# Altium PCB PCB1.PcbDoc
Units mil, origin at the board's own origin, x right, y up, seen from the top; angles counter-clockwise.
Board outline 2495 x 1003.43 mil, 4 copper layers (Top Layer, GND, 3.3V, Bottom Layer), stack 61.581 mil thick; 63 components, 70 nets, 242 pads, 36 vias.
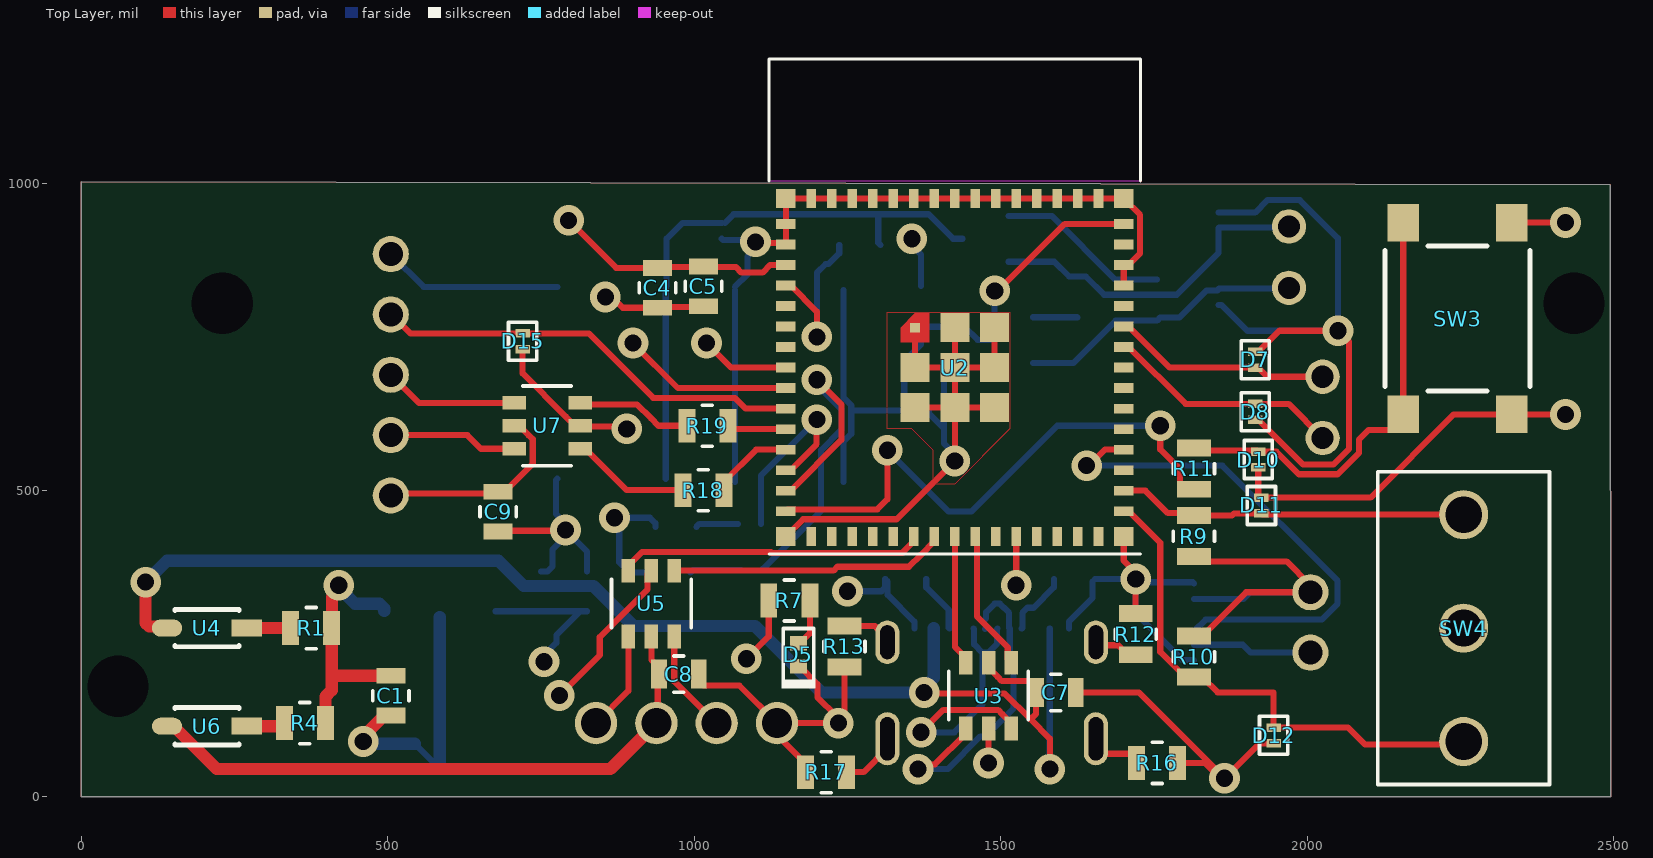
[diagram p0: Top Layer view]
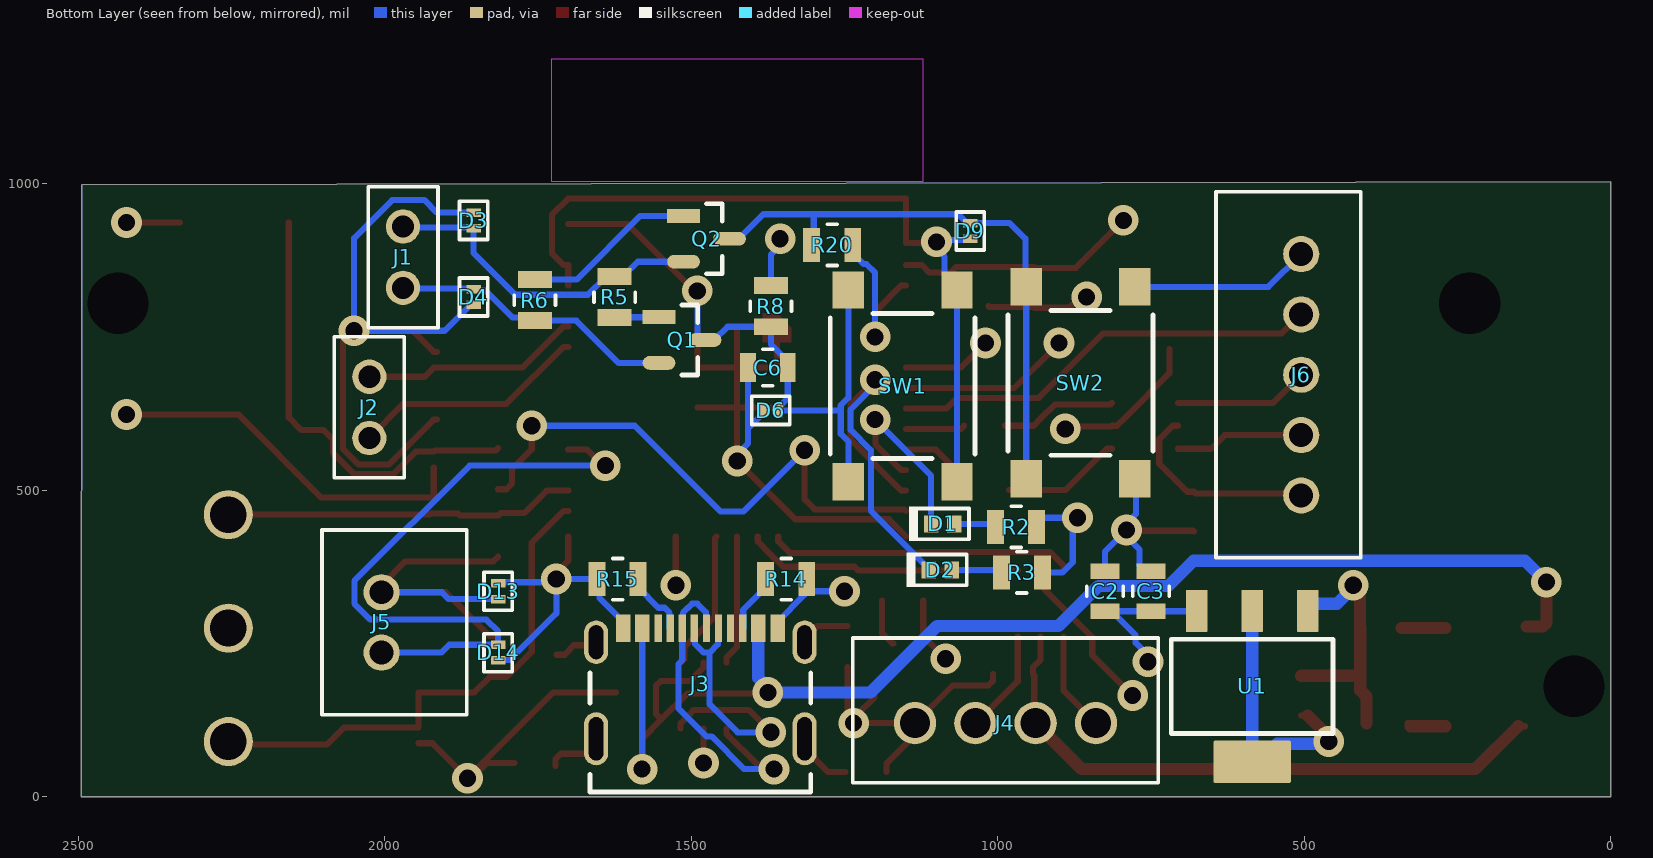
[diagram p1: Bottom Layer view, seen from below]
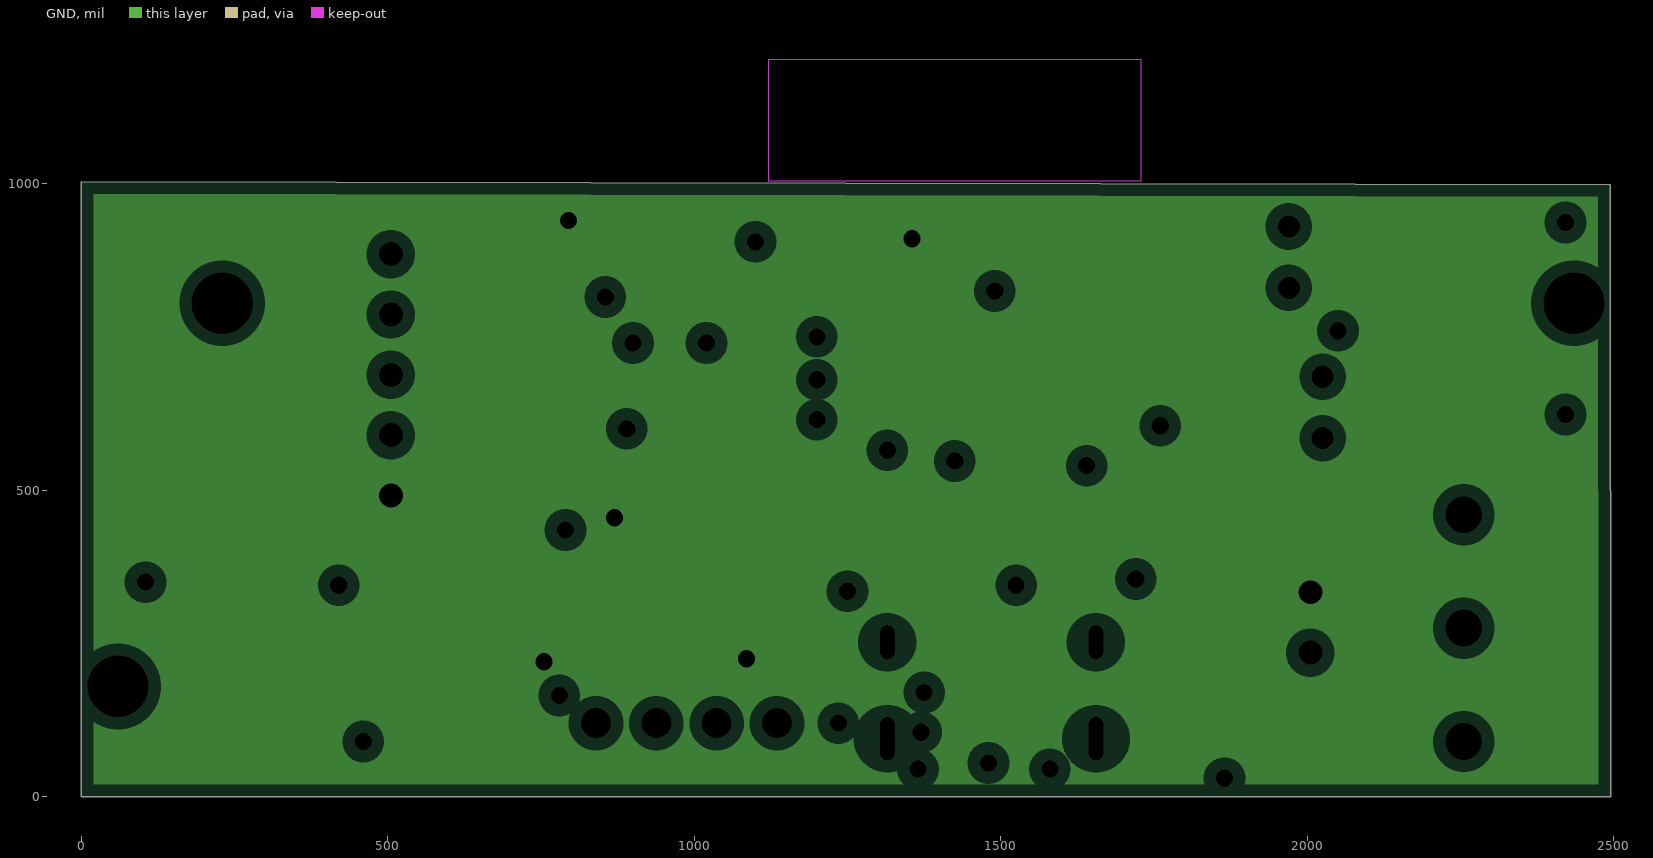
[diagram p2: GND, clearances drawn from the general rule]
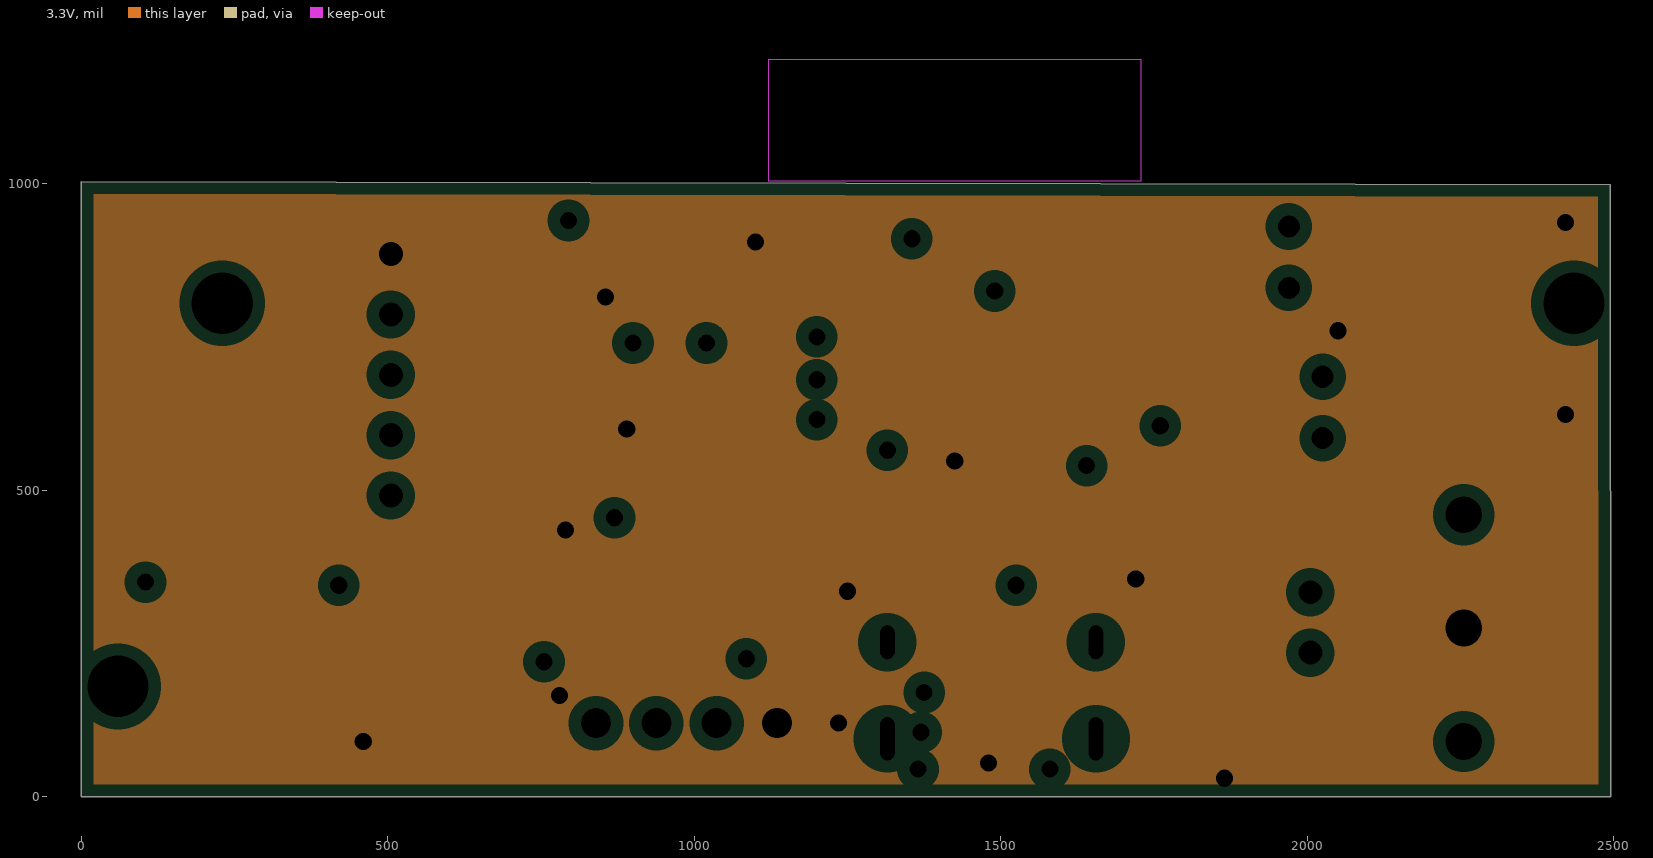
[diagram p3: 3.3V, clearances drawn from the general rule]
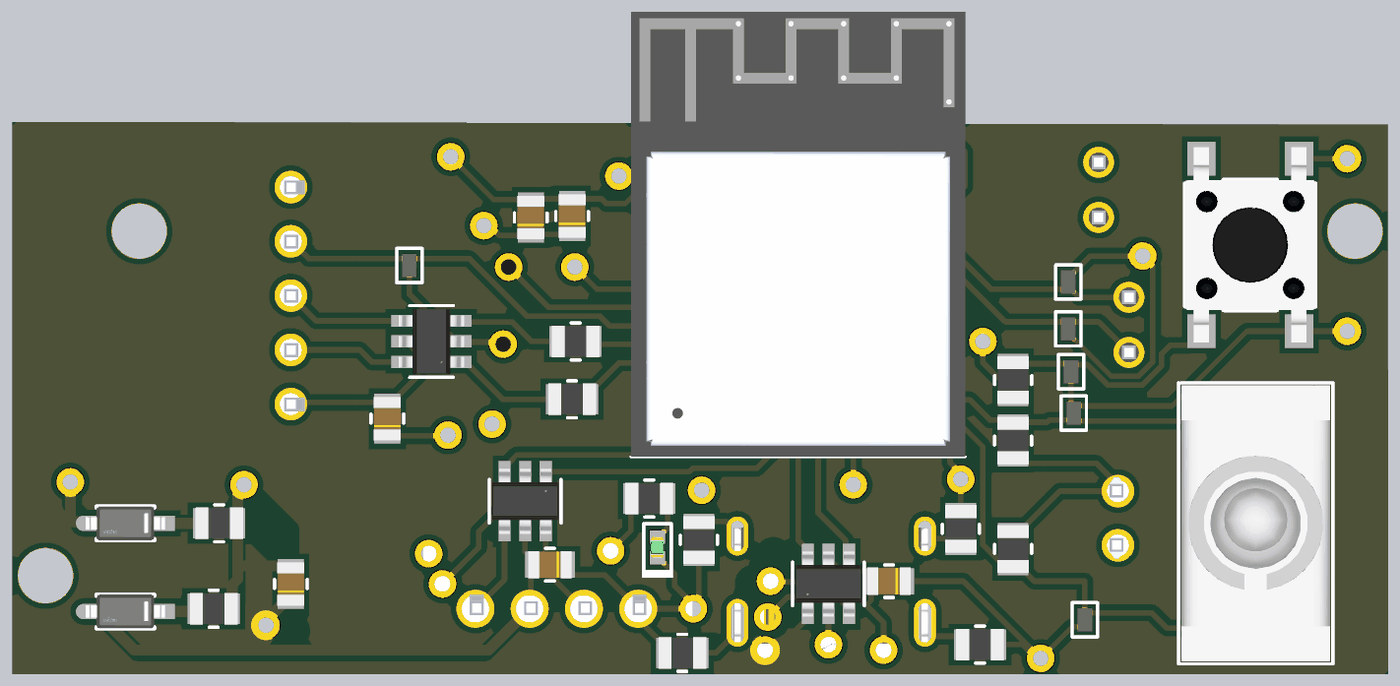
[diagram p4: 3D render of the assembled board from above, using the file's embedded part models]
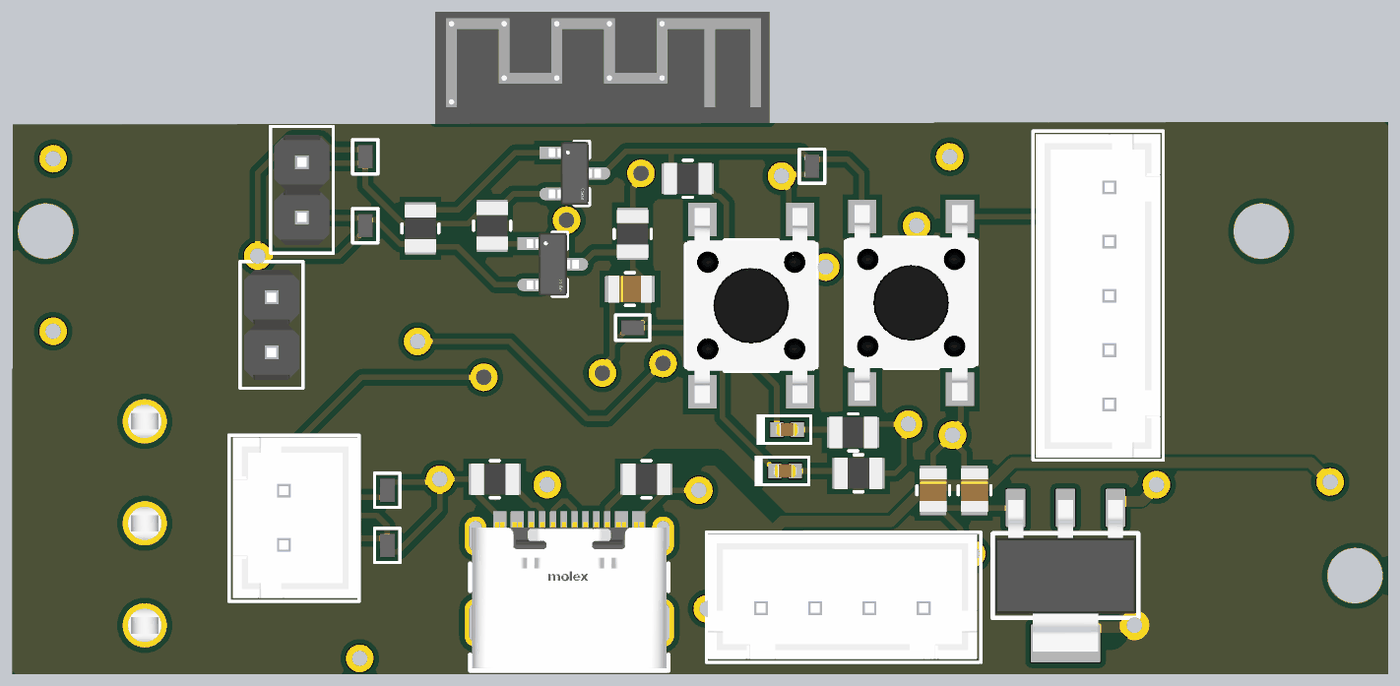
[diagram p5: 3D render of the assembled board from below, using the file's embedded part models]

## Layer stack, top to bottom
Top Solder: solder mask 0.4, Solder Resist, Dk 3.5
Top Layer: signal copper 1.378
Dielectric 2: prepreg 3.913, PP-006, Dk 4.1
GND: plane copper 0.598, net 3.3V
Dielectric 1: dielectric 49.803, FR-4, Dk 4.8
3.3V: plane copper 0.598, net GND
Dielectric 3: prepreg 3.913, PP-006, Dk 4.1
Bottom Layer: signal copper 1.378
Bottom Solder: solder mask 0.4, Solder Resist, Dk 3.5

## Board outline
0,0 0,1003.43 2494.51,998.13 2495,0

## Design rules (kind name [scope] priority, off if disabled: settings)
Clearance [All] p1: gap=10 ignorepadtopadclearanceinfootprint=FALSE except(6: Arc-Arc Arc-Track Arc-SMDPad Track-Track Track-SMDPad SMDPad-SMDPad)
PlaneClearance [All] p1: clearance=20
PlaneConnect [All] p1: planeconnectstyle=Relief reliefexpansion=20 reliefentries=4 reliefconductorwidth=10 reliefairgap=10
PolygonConnect [All] p1: connectstyle=Relief reliefconductorwidth=10 reliefentries=4 polygonreliefangle="90 Angle" airgapwidth=10
RoutingVias [All] p1: holewidth=12 width=24 viastyle="Through Hole" minholewidth=12 minwidth=24 maxholewidth=12 maxwidth=24
SolderMaskExpansion [All] p1: expansion=2 istentingtop=FALSE
SupplyNets "Schematic Supply Nets_2" [InNet('+5V_VBUS')] p1: voltage=0.000
SupplyNets "Schematic Supply Nets_1" [InNet('GND')] p2: voltage=0.000
Width [All] p1: maxlimit=100 minlimit=10 preferedwidth=10 minimp=50.000000 maximp=50.000000 favimp=50.000000
28 further rules are at their usual default settings.

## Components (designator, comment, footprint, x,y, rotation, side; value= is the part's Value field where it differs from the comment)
C1 "4.7 uF" CAP_CL21_SAM-L 505,165 r90 top value=4.7µF
C2 "10 uF" CAP_CL21_SAM-L 825,335 r270 bottom value=10µF
C3 "10 uF" CAP_CL21_SAM-L 750,335 r270 bottom value=10µF
C4 "10 uF" CAP_CL21_SAM-L 940,830 r90 top value=10µF
C5 ".1 uF" CAP_CL21_SAM-L 1015,832.48 r90 top value=100nF
C6 "1 uF" CAP_CL21_SAM-L 1375,700 r180 bottom value=1µF
C7 ".1 uF" CAP_CL21_SAM-L 1590,170 r180 top value=100nF
C8 ".1 uF" CAP_CL21_SAM-L 975,200 r180 top value=100nF
C9 ".1 uF" CAP_CL21_SAM-L 680,465 r90 top value=100nF
D1 "RED" LED0402R 1090,445 r180 bottom
D2 "RED" LED0402R 1093.7,370 r180 bottom
D3 "AQ3045-01ETG" SOD882 1855,940 r270 bottom
D4 "AQ3045-01ETG" SOD882 1855,815 r90 bottom
D5 "GREEN" LED0402G 1170,231.3 r90 top
D6 "AQ3045-01ETG" SOD882 1370,630 r180 bottom
D7 "AQ3045-01ETG" SOD882 1915,712.79 r270 top
D8 "AQ3045-01ETG" SOD882 1915,627.79 r90 top
D9 "AQ3045-01ETG" SOD882 1044.92,922.8 r90 bottom
D10 "AQ3045-01ETG" SOD882 1920,550 r90 top
D11 "AQ3045-01ETG" SOD882 1925,475 r270 top
D12 "AQ3045-01ETG" SOD882 1945,100 r90 top
D13 "AQ3045-01ETG" SOD882 1815,335 r270 bottom
D14 "AQ3045-01ETG" SOD882 1815,235 r90 bottom
D15 "AQ3045-01ETG" SOD882 720,742.8 r90 top
J1 "M20-9990246" CONN2_M20-999_1X2_HRW 1970,930 r90 bottom
J2 "M20-9990246" CONN2_M20-999_1X2_HRW 2025,585 r270 bottom
J3 "217179-0001" FP-2171790001-MFG 1485,139.76 r180 bottom
J4 "455-B4B-XH-A-ND" CONN_B4B-XH-A_JST 839.72,120 r180 bottom
J5 "B2B-XH-A" CONN_B2B-XH-A_JST 2005,235 r270 bottom
J6 "455-B5B-XH-A-ND" CONN_B5B-XH-A_JST 505,885 r90 bottom
Q1 "SS8050-G" FP-SS8050-G-IPC_B 1515,745 r180 bottom
Q2 "SS8050-G" FP-SS8050-G-IPC_B 1475,910 r180 bottom
R1 "0" RES_1220_SUS-L 375,275 r0 top value=0Ω
R2 "1K" RES_1220_SUS-L 970,440 r180 bottom value=1kΩ
R3 "1K" RES_1220_SUS-L 960.5,365.75 r180 bottom value=1kΩ
R4 "0" RES_1220_SUS-L 365,120 r0 top value=0Ω
R5 "10K" RES_1220_SUS-L 1625,815 r270 bottom value=10kΩ
R6 "10K" RES_1220_SUS-L 1755,810 r90 bottom value=10kΩ
R7 "1K" RES_1220_SUS-L 1155,320 r180 top value=1kΩ
R8 "10K" RES_1220_SUS-L 1370,800 r90 bottom value=10kΩ
R9 "10K" RES_1220_SUS-L 1815,425 r270 top value=10kΩ
R10 "10K" RES_1220_SUS-L 1815,228.5 r90 top value=10kΩ
R11 "27" RES_1220_SUS-L 1815,535 r270 top value=27Ω
R12 "1MR" RES_1220_SUS-L 1720,265 r90 top value=1MΩ
R13 "1MR" RES_1220_SUS-L 1245,245 r270 top value=1MΩ
R14 "5.1K" RES_1220_SUS-L 1345,355 r0 bottom value=5.1kΩ
R15 "5.1K" RES_1220_SUS-L 1620,355 r180 bottom value=5.1kΩ
R16 "1MR" RES_1220_SUS-L 1755,55 r0 top value=1MΩ
R17 "1MR" RES_1220_SUS-L 1215,40 r180 top value=1MΩ
R18 "0" RES_1220_SUS-L 1015,500 r180 top value=0Ω
R19 "0" RES_1220_SUS-L 1021.5,605 r180 top value=0Ω
R20 "0" RES_1220_SUS-L 1270,900 r180 bottom value=0Ω
SW1 "PTS645SH50SMTR92LFS" FP-PTS645SH50SMTR92LFS-MFG 1155,670 r90 bottom
SW2 "PTS645SH50SMTR92LFS" FP-PTS645SH50SMTR92LFS-MFG 865,675 r90 bottom
SW3 "PTS645SH50SMTR92LFS" FP-PTS645SH50SMTR92LFS-MFG 2245,780 r90 top
SW4 "100SP1T1B4M2QE" 100SP1T1_EWI 2255,89.92 r180 top
U1 "TL1963A-33DCYR" DCY0004A_N 585,180 r270 bottom
U2 "ESP32-S3-MINI-1-N8" XCVR_ESP32-S3-MINI-1-N8 1425,700 r0 top
U3 "USBLC6-2SC6" SOT23-6L_STM 1480,165 r90 top value=2.5pF
U4 "1N5819HW-7-F" FP-SOD123-IPC_B 205,275 r180 top value=50pF
U5 "USBLC6-2SC6" SOT23-6L_STM 930,315 r270 top value=2.5pF
U6 "1N5819HW-7-F" FP-SOD123-IPC_B 205,115 r180 top value=50pF
U7 "USBLC6-2SC6" SOT23-6L_STM 760,605 r180 top value=2.5pF

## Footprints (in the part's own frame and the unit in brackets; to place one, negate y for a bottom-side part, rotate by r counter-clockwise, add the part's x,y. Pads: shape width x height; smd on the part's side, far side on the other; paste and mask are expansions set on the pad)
100SP1T1_EWI [mil]
  round 80 hole 60 paste-99999 mask+0: 1(0,0) 2(0,-185.04) 3(0,-370.08)
  silkscreen extent -140,-440 140,70, body extent -135,-435 135,65, height 1168
CAP_CL21_SAM-L [mm]
  rect 0.65x1.2 smd paste+0 mask+0: 1(-0.825,0) 2(0.825,0)
  silkscreen extent -0.2,-0.75 0.2,0.75, body extent -1,-0.63 1,0.63, height 1.35
CONN2_M20-999_1X2_HRW [mil]
  round 56 / inner round 60 / far side round 56 hole 36 paste-99999 mask+0: 1(0,0) 2(-100,0)
  silkscreen extent -165,-57 65,57, body extent -150,-50 50,50, height 223
CONN_B2B-XH-A_JST [mil]
  round 59 hole 39 paste-99999 mask+0: 1(0,0) 2(-98.43,0)
  silkscreen extent -200,-97 101,139, body extent -196,-90 96,136, height 276
CONN_B4B-XH-A_JST [mil]
  round 69 hole 49 paste-99999 mask+0: 1(0,0) 2(-98.43,0) 3(-196.85,0) 4(-295.28,0)
  silkscreen extent -397,-97 101,139, body extent -394,-91 94,135, height 276
CONN_B5B-XH-A_JST [mil]
  round 59 hole 39 paste-99999 mask+0: 1(0,0) 2(-98.42,0) 3(-196.85,0) 4(-295.28,0) 5(-393.7,0)
  silkscreen extent -495,-97 102,139, body extent -491,-92 96,134, height 276
DCY0004A_N [mm] "SOT223, 4-Leads, Body 6.7x3.7mm, Pitch 2.3mm, IPC Medium Density"
  rrect11% 1.75x0.9 smd: 1(-3.125,2.3) 2(-3.125,0) 3(-3.125,-2.3)
  rrect6% 1.75x3.2 smd: 4(3.125,0)
  silkscreen extent -1.95,-3.35 1.95,3.35, body extent -3.5,-3.25 3.5,3.25, height 1.62
FP-2171790001-MFG [mm]
  rect 0.6x1.15 smd paste+0 mask+0: A1B12(-3.2,3.425) A4B9(-2.4,3.425) B1A12(3.2,3.425) B4A9(2.4,3.425)
  rect 0.3x1.15 smd paste+0 mask+0: A5(-1.25,3.425) A6(-0.25,3.425) A7(0.25,3.425) A8(1.25,3.425) B5(1.75,3.425) B6(0.75,3.425) B7(-0.75,3.425) B8(-1.75,3.425)
  rrect100% 1x1.8 hole 1.4 slot 0.6 at 0 deg paste-2539.97 mask+0: S1(-4.32,2.85) S2(4.32,2.85)
  rrect100% 1x2.2 hole 1.8 slot 0.6 at 0 deg paste-2539.97 mask+0: S3(-4.32,-1.15) S4(4.32,-1.15)
  silkscreen extent -4.57,-3.35 4.57,1.58, body extent -4.47,-3.25 4.47,3.5, height 3.36
FP-PTS645SH50SMTR92LFS-MFG [mm]
  rect 1.55x1.3 smd paste+0 mask+0: 1(-3.975,2.25) 2(3.975,2.25) 3(-3.975,-2.25) 4(3.975,-2.25)
  silkscreen extent -3,-3 3,3, body extent -4.5,-3 4.5,3, height 4.3
FP-SOD123-IPC_B [mil]
  rect 49.51x27.66 smd paste+0 mask+0: 1(-64.98,0)
  rrect100% 49.51x27.66 smd paste+0 mask+0: 2(64.98,0)
  silkscreen extent -52,-31 52,31, body extent -100,-40 100,40, height 10
FP-SS8050-G-IPC_B [mm]
  rect 1.357x0.572 smd paste+0 mask+0: 1(-0.951,0.95)
  rrect100% 1.357x0.572 smd paste+0 mask+0: 2(-0.951,-0.95) 3(0.951,0)
  silkscreen extent 0,-1.45 0.65,1.45, body extent -1.21,-1.45 1.21,1.45, height 1.15
LED0402G [mm]
  rect 0.6x0.7 smd: 1(-0.475,0) 2(0.475,0)
  silkscreen extent -1.4,-0.71 1.09,0.71, body extent -0.5,-0.3 0.5,0.3, height 0.21
LED0402R [mm]
  rect 0.6x0.7 smd: 1(-0.475,0) 2(0.475,0)
  silkscreen extent -1.4,-0.71 1.09,0.71, body extent -0.5,-0.3 0.5,0.3, height 0.21
RES_1220_SUS-L [mil]
  rect 27.62x55.09 smd paste+0 mask+0: 1(-33.5,0) 2(33.5,0)
  silkscreen extent -8,-34 8,34, body extent -43,-29 43,29, height 28
SOD882 [mm]
  rect 0.35x0.6 smd: 1(-0.325,0) 2(0.325,0)
  silkscreen extent -0.79,-0.58 0.79,0.58, body extent -0.54,-0.34 0.54,0.34, height 0.44
SOT23-6L_STM [mil]
  rect 38.5x22 smd paste+0 mask+0: 1(-53.75,37.4) 2(-53.75,0) 3(-53.75,-37.4) 4(53.75,-37.4) 5(53.75,0) 6(53.75,37.4)
  silkscreen extent -40,-65 40,65, body extent -59,-60 59,60, height 57
XCVR_ESP32-S3-MINI-1-N8 [mm]
  rect 0.8x0.4 smd: 1(-7,5.95) 2(-7,5.1) 3(-7,4.25) 4(-7,3.4) 5(-7,2.55) 6(-7,1.7) 7(-7,0.85) 8(-7,0) 9(-7,-0.85) 10(-7,-1.7) 11(-7,-2.55) 12(-7,-3.4) 13(-7,-4.25) 14(-7,-5.1) 15(-7,-5.95) 31(7,-5.95) 32(7,-5.1) 33(7,-4.25) 34(7,-3.4) 35(7,-2.55) 36(7,-1.7) 37(7,-0.85) 38(7,0) 39(7,0.85) 40(7,1.7) 41(7,2.55) 42(7,3.4) 43(7,4.25) 44(7,5.1) 45(7,5.95)
  rect 0.4x0.8 smd: 16(-5.95,-7) 17(-5.1,-7) 18(-4.25,-7) 19(-3.4,-7) 20(-2.55,-7) 21(-1.7,-7) 22(-0.85,-7) 23(0,-7) 24(0.85,-7) 25(1.7,-7) 26(2.55,-7) 27(3.4,-7) 28(4.25,-7) 29(5.1,-7) 30(5.95,-7) 46(5.95,7) 47(5.1,7) 48(4.25,7) 49(3.4,7) 50(2.55,7) 51(1.7,7) 52(0.85,7) 53(0,7) 54(-0.85,7) 55(-1.7,7) 56(-2.55,7) 57(-3.4,7) 58(-4.25,7) 59(-5.1,7) 60(-5.95,7)
  rect 1.2x1.2 smd: 61(0,0) 67(0,1.65) 68(1.65,1.65) 69(-1.65,0) 70(1.65,0) 71(-1.65,-1.65) 72(0,-1.65) 73(1.65,-1.65)
  rect 0.8x0.8 smd: 62(-7,7) 63(-7,-7) 64(7,-7) 65(7,7)
  rect 0.4x0.4 smd paste-1 mask+0: 66(-1.65,1.65)
  Top Layer region: -1.05,1.05 -2.25,1.05 -2.25,1.65 -1.65,2.25 -1.05,2.25
  Keep-Out Layer region: 7.7,7.725 -7.7,7.725 -7.7,12.775 7.7,12.775
  Keep-Out Layer region: 7.7,7.725 -7.7,7.725 -7.7,12.775 7.7,12.775
  silkscreen extent -7.7,-7.73 7.7,12.77, body extent -7.7,-7.73 7.7,12.78, height 2.55

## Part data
C1: library part CL21A475KAQNNNE, "25V 4.7uF X5R ±10% 0805 Multilayer Ceramic Capacitors MLCC - SMD/SMT ROHS", Case Code (Imperial)=0805, Case Code (Metric)=2012, Dielectric=X5R, Dielectric Material=Ceramic, Manufacturer="Samsung Electro-Mechanics", Max Operating Temperature=85°C, Min Operating Temperature=-55°C, Supplier Part Number=1276-1244-6-ND, Tolerance=10%, Voltage Rating=25V
C2 C3 C4: library part CL21B106KOQNNNE, "16V 10uF X7R ±10% 0805 Multilayer Ceramic Capacitors MLCC - SMD/SMT ROHS", Case Code (Imperial)=0805, Case Code (Metric)=2012, Dielectric=X7R, Dielectric Material=Ceramic, Manufacturer="Samsung Electro-Mechanics", Max Operating Temperature=125°C, Min Operating Temperature=-55°C, Supplier Part Number=1276-2872-6-ND, Tolerance=10%, Voltage=16V
C5 C7 C8 C9: library part CL21B104KBCNNNC, "50V 100nF X7R ±10% 0805 Multilayer Ceramic Capacitors MLCC - SMD/SMT ROHS", Case Code (Imperial)=0805, Case Code (Metric)=2012, Dielectric=X7R, Dielectric Material=Ceramic, Manufacturer="Samsung Electro-Mechanics", Max Operating Temperature=125°C, Min Operating Temperature=-55°C, Supplier Part Number=1276-1003-6-ND, Tolerance=10%, Voltage=50V
C6: library part CL21B105KBFNNNE, "50V 1uF X7R ±10% 0805 Multilayer Ceramic Capacitors MLCC - SMD/SMT ROHS", Case Code (Imperial)=0805, Case Code (Metric)=2012, Dielectric=X7R, Dielectric Material=Ceramic, Manufacturer="Samsung Electro-Mechanics", Max Operating Temperature=125°C, Min Operating Temperature=-55°C, Supplier Part Number=1276-1029-6-ND, Tolerance=10%, Voltage=50V
D1 D2: library part VLMS1500-GS08, "LED RED 0402 SMD", Color=Red, Forward Current=30mA, Forward Voltage=2.4V, LCSC Part Number=C511370, Manufacturer=Vishay, Max Operating Temperature=85°C, Min Operating Temperature=-30°C, Reverse Voltage-Max=5V, Supplier Part Number=VLMS1500-GS08CT-ND
D3 D4 D6 D7 D8 D9 D10 D11 D12 D13 D14 D15: "TVS DIODE 5.3VWM 12VC SOD882", LCSC Part Number=C3710326, Manufacturer=Littelfuse, Max Breakdown Voltage=9V, Max Operating Temperature=150°C, Min Breakdown Voltage=6.8V, Min Operating Temperature=-55°C, Non-rep Peak Rev Power Dis-Max=40W, Package Body Material=Plastic, Package Shape=Rectangular, Package Style="CHIP CARRIERMeter", Rep Pk Reverse Voltage-Max=5.3V, Supplier Part Number=F9321CT-ND
D5: library part VLMG1500-GS08, "LED YLW-GRN 0402 SMD", Case Code (Imperial)=0402, Case Code (Metric)=1005, Color=Green,Yellow, Forward Current=30mA, Forward Voltage=2V, Illumination Color=Green, LCSC Part Number=C511404, Lens Color=Clear, Manufacturer=Vishay, Max Operating Temperature=85°C, Min Operating Temperature=-30°C, Package Quantity=1, Power Dissipation=75mW, Reverse Voltage=5V, Supplier Part Number=VLMG1500-GS08CT-ND, Test Current=20mA
J1 J2: "Connector Header Through Hole 2 position 0.100\" (2.54mm)", Case/Package=SIL, Color=Black, Contact Resistance=30mΩ, Current Rating=3A, Dielectric Material=Polyamide, Insulation Resistance=1GΩ, Manufacturer=Harwin, Max Operating Temperature=105°C, Min Operating Temperature=-40°C, Supplier Part Number=952-2262-ND, Voltage Rating (AC)=750V
J3: "CONN RCP USB2.0 TYP C 24P SMD RA", LCSC Part Number=C3197684, Manufacturer=Molex, Supplier Part Number=900-2171790001CT-ND
J4: library part B4B-XH-A, "Board Connector, 4 Contact(s), 1 Row(s), Male, Straight, Solder Terminal", Contact Resistance=20mΩ, Current Rating=3A, Insulation Resistance=1GΩ, Manufacturer=JST, Max Operating Temperature=85°C, Min Operating Temperature=-25°C
J5: "Board Connector, 2 Contact(s), 1 Row(s), Male, Straight, Solder Terminal", Contact Resistance=20mΩ, Current Rating=3A, Insulation Resistance=1GΩ, Manufacturer=JST, Max Operating Temperature=85°C, Min Operating Temperature=-25°C, Supplier Part Number=455-B2B-XH-A-ND
J6: library part B5B-XH-A, "Board Connector, 5 Contact(s), 1 Row(s), Male, Straight, 0.098 inch Pitch, Solder Terminal", Contact Resistance=20mΩ, Current Rating=3A, Insulation Resistance=1GΩ, Manufacturer=JST, Max Operating Temperature=85°C, Min Operating Temperature=-25°C
Q1 Q2: "TRANS NPN 25V 1.5A SOT23-3", LCSC Part Number=C164886, Manufacturer=Comchip, Supplier Part Number=641-1790-1-ND
R1 R4 R18 R19 R20: library part RC0805JR-070RL, "GENERAL PURPOSE CHIP RESISTOR Metal Glaze/thick Film, 0.125W, 0ohm, Surface Mount, 0805", Case Code (Imperial)=0805, Manufacturer="Yageo Group", Max Operating Temperature=155°C, Min Operating Temperature=-55°C, Power Dissipation=125mW, Supplier Part Number=311-0.0ARDKR-ND, Temperature Coefficient=300ppm/°C, Tolerance=5%, Voltage Rating=150V
R2 R3 R7: library part RG2012P-102-B-T5, "Res Thin Film 0805 1K Ohm 0.1% 0.125W(1/8W) ±25ppm/C Sulfur Resistant Pad SMD Automotive T/R", Case Code (Imperial)=0805, Case Code (Metric)=2012, Manufacturer=Susumu, Max Operating Temperature=155°C, Max Power Dissipation=125mW, Min Operating Temperature=-55°C, Supplier Part Number=RG20P1.0KBCT-ND, Temperature Coefficient=25ppm/°C, Tolerance=0.1%, Voltage Rating=150V
R5 R6 R8 R9 R10: library part RG2012P-103-B-T5, "Res Thin Film 0805 10K Ohm 0.1% 0.125W(1/8W) ±25ppm/C Sulfur Resistant Pad SMD Automotive T/R", Case Code (Imperial)=0805, Case Code (Metric)=2012, Manufacturer=Susumu, Max Operating Temperature=155°C, Min Operating Temperature=-55°C, Power Dissipation=125mW, Supplier Part Number=RG20P10.0KBCT-ND, Temperature Coefficient=25ppm/°C, Tolerance=0.1%, Voltage Rating=150V
R11: library part RG2012Q-270-D-T5, "Fixed Resistor, Thin Film, 0.125W, 27ohm, 150V, 0.5% +/-Tol, 50ppm/Cel, Surface Mount, 0805", Case Code (Imperial)=0805, Case Code (Metric)=2012, Manufacturer=Susumu, Max Operating Temperature=155°C, Min Operating Temperature=-55°C, Power Dissipation=125mW, Supplier Part Number=408-RG2012Q-270-D-T5CT-ND, Temperature Coefficient=50ppm/°C, Tolerance=0.5%, Voltage Rating=150V
R12 R13 R16 R17: library part RG2012P-105-B-T5, "Res Thin Film 0805 1M Ohm 0.1% 0.125W(1/8W) ±25ppm/C Sulfur Resistant Pad SMD Automotive T/R", Case Code (Imperial)=0805, Case Code (Metric)=2012, Manufacturer=Susumu, Max Operating Temperature=155°C, Min Operating Temperature=-55°C, Power Dissipation=125mW, Supplier Part Number=408-RG2012P-105-B-T5CT-ND, Temperature Coefficient=25ppm/°C, Tolerance=0.1%, Voltage Rating=150V
R14 R15: library part RG2012P-512-B-T5, "Res Thin Film 0805 5.1K Ohm 0.1% 0.125W(1/8W) ±25ppm/C Sulfur Resistant Pad SMD Automotive T/R", Case Code (Imperial)=0805, Case Code (Metric)=2012, Manufacturer=Susumu, Max Operating Temperature=155°C, Max Power Dissipation=125mW, Min Operating Temperature=-55°C, Supplier Part Number=RG20P5.1KBDKR-ND, Temperature Coefficient=25ppm/°C, Tolerance=0.1%, Voltage Rating=150V
SW1 SW2 SW3: "SWITCH TACTILE SPST-NO 0.05A 12V", Contact Current(DC)-Max=50mA, Contact DC Max Rating R Load=0.05A@12VDC, Contact Resistance=0.1mR, Contact Voltage(DC)-Max=12V, Dielectric Withstand Volts=250VACV, Insulation Resistance=100GR, LCSC Part Number=C221869, Manufacturer="ITT C&K", Manufacturer Series=PTS645, Max Operating Temperature=60°C, Min Operating Temperature=-20°C, Supplier Part Number=CKN9085CT-ND
SW4: "Switch Toggle ON None ON SPDT Round Lever PC Pins 5A 250VAC 28VDC PC Mount", Contact Current Rating=5A, Contact Voltage Rating (AC)=120V, Manufacturer=E-Switch, Max Operating Temperature=85°C, Max Voltage Rating (DC)=28V, Min Operating Temperature=-30°C, Supplier Part Number=EG2355-ND
U1: "IC REG LINEAR 3.3V 1.5A SOT223-4", Case/Package=SOP, Dropout Voltage1-Max=550mV, Dropout Voltage1-Nom=340mV, Input Voltage Absolute-Max=20V, LCSC Part Number=C181262, Manufacturer="Texas Instruments", Min Input Voltage=3.8V, Operating Temperature, TJ-Max=125°C, Operating Temperature, TJ-Min=-40°C, Output Current1-Max=1.5A, Output Voltage1-Max=3.4V, Output Voltage1-Min=3.2V, Output Voltage1-Nom=3.3V, Package Body Material=Plastic, Package Shape=Rectangular, Package Style="SMALL OUTLINEMeter", Peak Reflow Temperature (Cel)=260°C, Supplier Part Number=296-24897-1-ND, Voltage Tolerance-Max=3%
U2: "SMD Module, ESP32-S3FN8, 8 mb Sp", LCSC Part Number=C2913206, Manufacturer="Espressif Systems", Supplier Part Number=1965-ESP32-S3-MINI-1-N8CT-ND
U3 U5 U7: "17V Clamp 5A (8/20µs) Ipp Tvs Diode Surface Mount SOT-23-6", Breakdown Voltage=6V, Case/Package=SOT-23, Clamping Voltage=17V, Forward Voltage=1.1V, Leakage Current=150nA, Manufacturer=STMicroelectronics, Max Junction Temperature (Tj)=125°C, Max Repetitive Reverse Voltage (Vrrm)=5.25V, Min Operating Temperature=-40°C, Peak Pulse Current=5A, Power Line Protection=Yes, Reverse Standoff Voltage=5V, Supplier Part Number=497-5235-1-ND, Test Current=1mA
U4 U6: "DIODE SCHOTTKY 40V 1A SOD123", Average Rectified Current=1A, Case/Package=SOD-123-2, Forward Voltage=750mV, Manufacturer="Diodes Inc.", Max Forward Surge Current (Ifsm)=25A, Max Junction Temperature (Tj)=125°C, Max Power Dissipation=450mW, Max Repetitive Reverse Voltage (Vrrm)=40V, Min Operating Temperature=-65°C, Peak Reverse Current=1mA, Supplier Part Number=1N5819HW-FDICT-ND

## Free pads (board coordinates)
  round 60 hole 100: 2(60,180) 2(230,805) 2(2435,805)

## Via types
v1: diameter 50, hole 28, Top Layer to Bottom Layer, 35 vias
v2: diameter 50/50 (per signal layer), hole 28, Top Layer to Bottom Layer, 1 vias

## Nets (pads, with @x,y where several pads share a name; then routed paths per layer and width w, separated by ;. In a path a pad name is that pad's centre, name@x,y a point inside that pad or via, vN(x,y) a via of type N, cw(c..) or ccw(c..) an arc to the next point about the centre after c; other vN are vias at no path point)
3.3V: C2.2 C3.2 C4.2 C5.2 C9.2 D13.2 J5.2 J6.5 R2.2 R3.2 R7.2 R8.2 R9.2 R10.2 U1.3 U2.3 U7.5 | length 2021
  Top Layer w10: J6.5 508.09,494.39 676.91,494.39 C9.2 690.83,497.48 736.5,543.15 736.5,583.15 730.06,589.6 729.9,589.6 714.5,605 U7.5 ; v1(795,940) 872.52,862.48 C4.2 941.24,863.72 1068.24,863.72 1076.96,855 1111.57,855 1123.89,867.32 U2.3 ; v1(1085,225) 1121.5,261.5 R7.2 ; R10.2 1828.73,261.99 1900.17,333.43 J5.2 2005,345 1966.24,383.76 1822.74,383.76 R9.2
  Bottom Layer w10: U1.3 676.06,302.52 C3.2 C2.2@814.17,302.52 ; v1(755,220) 755,230.82 775.15,250.97 775.15,263.49 C2.2@814.17,302.52 ; C2.2 C2.2@814.17,302.52 ; R3.2 894.25,365.75 877.65,382.35 877.65,447.35 v1(870,455) 927.69,455 936.5,446.19 R2.2 ; v1(1355,910) 1355,899.18 1370,884.18 R8.2 ; D13.2 1895.53,322.2 1906.75,333.43 J5.2
+5V_VBUS: C7.2 J3.A4B9 J3.B4A9 U3.5 U4.2 | length 2261.9
  Top Layer w10: U4.2@137.47,277.55 U4.2 ; v1(1375,170) 1376.5,168.5 1505.96,168.5 1548.48,125.98 ; U3.5 1480,210.5 1494.77,195.73 1494.77,195.57 1501.85,188.5 1549.72,188.5 1557.52,180.7 C7.2 1557.52,135.02 1548.48,125.98 ; v1(1580,45) 1580,94.46 1548.48,125.98
  Top Layer w20: v1(105,350) 105.02,283.41 110.88,277.55 U4.2@137.47,277.55
  Bottom Layer w10: J3.A4B9 1579.74,274.35 1579.74,45.26 v1(1580,45)
  Bottom Layer w20: v1(105,350) 140,385 680.51,385 721.82,343.68 835.81,343.68 901,278.49 1098.9,278.49 1207.38,170 v1(1375,170) 1375,178.12 1390.51,193.63 J3.B4A9
BTN_GPIO0: D9.2 Q2.3 R20.1 SW2.1 SW2.2 | length 954.3
  Bottom Layer w10: SW2.1 SW2.2 955,832.91 955,910 980.59,935.59 D9.2 ; D9.2@1049.84,935.59 1064.25,950 1300,950 ; R20.1 1300,903.5 1300,950 ; Q2.3 1422.12,910 1382.12,950 1300,950
CHIP_PU: C6.2 D6.2 Q1.3 R8.1 SW1.1 SW1.2 U2.45 | length 1036.1
  Top Layer w10: v1(1490,825) 1495.42,825 1604.67,934.25 U2.45
  Bottom Layer w10: SW1.1 1243.58,579.39 1256,591.8 1256,630 ; SW1.2 1243.58,650.61 1256,638.2 1256,630 ; R8.1@1370,762.4 1370,737.69 1350.93,718.62 1350.32,718.62 1342.52,710.83 C6.2 1342.52,649.61 1357.2,634.92 D6.2 1256,630 ; R8.1 1440.62,766.5 1462.12,745 Q1.3 1484.21,745 1490,750.79 v1(1490,825)
DTR_FTDI: D3.2 J1.1 Q2.2 R5.1 | length 549.8
  Bottom Layer w10: Q2.2 1587.17,872.6 1611.27,848.5 R5.1 1638.73,848.5 1668.54,818.68 1787.1,818.68 1855,886.59 D3.2 1856.4,928.6 1968.6,928.6 J1.1
GND: C1.1 C2.1 C3.1 C4.1 C5.1 C6.1 C7.1 C8.1 C9.1 D3.1 D4.1 D5.1 D6.1 D7.1 D8.1 D9.1 D10.1 D11.1 D12.1 D13.1 D14.1 D15.1 J3.A1B12 J3.B1A12 J4.4 J6.1 R12.2 R13.2 R14.1 R15.1 R16.2 R17.2 SW1.3 SW1.4 SW2.3 SW2.4 SW3.3 SW3.4 SW4.2 U1.2 U1.4 U2.1 U2.2 U2.42 U2.43 U2.46 U2.47 U2.48 U2.49 U2.50 U2.51 U2.52 U2.53 U2.54 U2.55 U2.56 U2.57 U2.58 U2.59 U2.60 U2.61 U2.62 U2.63 U2.64 U2.65 U2.66 U2.67 U2.68 U2.69 U2.70 U2.71 U2.72 U2.73 U3.2 U5.2 U7.2 | length 7956.3
  Top Layer w10: v2(460,90) v2@460,98.35 ; C1.1@494.17,132.52 C1.1 ; C9.1 681.24,433.76 788.76,433.76 v1(790,435) ; D15.1 720,690.35 790.57,619.77 790.73,619.77 805.5,605 U7.2 814.75,604 886,604 v1(890,600) ; v1(780,165) 845.83,230.83 845.83,260.29 924,338.46 924,362.75 U5.2 ; v1(855,815) 865.82,815 883.3,797.52 C4.1 941.24,798.76 1013.76,798.76 C5.1 ; C8.1 1007.48,189.17 1015.28,181.38 1073.62,181.38 J4.4 ; v1(1100,905) 1102.11,902.89 1148.64,902.89 1149.41,903.66 U2.1 U2.62 U2.60 U2.59 U2.58 U2.57 U2.56 U2.55 U2.54 U2.53 U2.52 U2.51 U2.50 U2.49 U2.48 U2.47 U2.46 U2.65 1727.34,948.84 1727.34,886.2 1708.46,867.32 U2.43 U2.42 ; U2.63 1177.62,452.62 1330.1,452.62 v1(1425,547.52) U2.72 ; D5.1 1171.97,212.6 1200.98,183.59 1200.98,162.14 1232.17,130.95 v1@1232.17,122.83 ; R17.2 1181.5,53.73 1144.38,90.86 1144.38,110.62 J4.4 ; R13.2 1245,138.12 1235,128.12 v1(1235,120) J4.4 ; U2.71 U2.72 ; U2.66 U2.69 U2.61 ; U2.67 U2.61 ; v1(1480,55) U3.2 ; U2.73 U2.72 ; U2.68 U2.70 U2.61 ; C7.1 1725,170 v1(1865,30) ; U2.64 1700.59,385.23 1720,365.82 v1(1720,355) R12.2 ; R16.2 1832.31,55 1857.31,30 v1(1865,30) ; D8.1 1919.92,615 1992.92,542 2042.81,542 2068,567.19 2068,742 v1(2050,760) 1954.33,760 1919.92,725.59 D7.1 ; D10.1 1920,489.69 1921.89,487.8 D11.1 2103.19,487.8 2238.9,623.5 v1(2421.1,623.5) ; D12.1 1922.2,87.2 v1(1865,30) ; SW3.4 v1(2421.1,936.5) ; U2.72 U2.61
  Top Layer w20: v2@460,98.35 C1.1@494.17,132.52
  Bottom Layer w10: v2(460,90) v2@463.58,86.42 ; J6.1 558.5,831.5 SW2.4 ; U1.4@543.86,86.42 U1.4@585,45.28 ; C3.1 760.83,367.48 768.62,375.28 768.62,402.8 790,424.18 v1(790,435) ; SW2.3 774.74,516.83 774.74,461.08 790,445.82 v1(790,435) ; v1(780,165) v1@780,175.82 ; C2.1 825,400 v1(790,435) ; D9.1 1046.81,908.11 1096.89,908.11 v1(1100,905) 1100,894.18 1087.01,881.18 1087.01,852.01 SW1.4@1066.42,831.42 ; SW1.3 SW1.4 ; v1(1250,335) 1305.24,335 1311.5,341.27 1311.5,351.19 R14.1 1315.32,351.19 1315.32,341.27 1315.32,329.13 1359.02,285.43 J3.B1A12 ; D6.1 1382.79,625.08 1407.48,600.39 ; C6.1 1407.48,600.39 ; v1(1425,547.52) 1425,558.34 1407.48,575.86 1407.48,600.39 ; J3.A1B12 1610.98,285.43 1649.68,324.13 R15.1@1649.68,351.19 ; R15.1 v1(1720,355) ; D14.1 1814.15,223.05 1795.94,223.05 1720,298.99 v1(1720,355) ; D13.1 1813.11,349.69 1725.31,349.69 v1(1720,355) ; D4.1 1859.92,802.2 1902.13,760 v1(2050,760) 2050,910.81 1987.81,973 1934.91,973 1914.71,952.8 D3.1
  Bottom Layer w20: v2@463.58,86.42 U1.4@543.86,86.42 ; U1.4@585,46.97 U1.2@585,293.03
GPIO0: R20.2 U2.4 | length 277.4
  Top Layer w10: U2.4 1157.28,833.86 1200,791.14 v1(1200,750)
  Bottom Layer w10: v1(1200,750) 1200,854.57 1214.06,868.64 1218.87,868.64 1236.5,886.27 R20.2
GPIO1: U2.5
GPIO2: U2.6
GPIO3: U2.7
GPIO4: U2.8 | length 146
  Top Layer w10: v1(1020,740) 1060,700 U2.8
GPIO5: U2.9 | length 279.8
  Top Layer w10: v1(900,740) 973.46,666.54 U2.9
GPIO6: D15.2 J6.2 U2.10 | length 708
  Top Layer w10: J6.2 505.96,786.58 536.95,755.59 D15.2 827.84,755.59 932.9,650.54 1066.37,650.54 1083.84,633.07 U2.10
GPIO7: R19.1 U2.11 | length 96.6
  Top Layer w10: R19.1 1060.39,599.61 U2.11
GPIO8: R18.1 U2.12 | length 136.4
  Top Layer w10: R18.1 1048.5,513.73 1100.91,566.14 U2.12
GPIO9: D1.1 U2.13 | length 315.7
  Top Layer w10: U2.13 1157.28,532.68 1199.61,575 1199.61,614.61 v1(1200,615)
  Bottom Layer w10: D1.1 1108.7,523.7 v1(1200,615)
GPIO10: D2.1 U2.14 | length 618.9
  Top Layer w10: U2.14 1157.28,499.21 1240,581.93 1240,640 v1(1200,680)
  Bottom Layer w10: D2.1 1112.4,371.97 1206.99,466.56 1206.99,565.42 1240,598.43 1240,631.57 1200,671.57 v1(1200,680)
GPIO11: R11.2 U2.15 | length 932.3
  Top Layer w10: U2.15 1152.28,468.62 1298.62,468.62 1315,485 v1(1315,565) ; v1(1760,605) 1760,566.59 1792.46,534.13 1792.46,510.31 1801.27,501.5 R11.2
  Bottom Layer w10: v1(1315,565) 1415,465 1452.09,465 1592.09,605 v1(1760,605)
GPIO12: U2.16
GPIO13: U2.17
GPIO14: U2.18
GPIO15: U2.19
GPIO16: U2.20
GPIO17: U2.21 U5.3 | length 499.2
  Top Layer w10: U5.3 892.6,377 908,392.4 908,392.56 914.44,399 1125.07,399 1126.41,397.66 1339.2,397.66 1358.07,416.54 U2.21
GPIO18: U2.22 U5.1 | length 451.8
  Top Layer w10: U5.1 1227.18,368.75 1233.43,375 1350,375 1370,395 1391.54,416.54 U2.22
GPIO19: U2.23 U3.6 | length 212.9
  Top Layer w10: U2.23 1425,244.6 1442.6,227 U3.6
GPIO20: U2.24 U3.4 | length 230.1
  Top Layer w10: U2.24 1461.34,421.54 1461.34,293.66 1511.4,243.6 1511.4,224.75 U3.4
GPIO21: U2.25
GPIO26: U2.26 | length 79.6
  Top Layer w10: v1(1525,345) 1525.2,345.2 1525.2,424.21 U2.26
GPIO33: U2.28
GPIO34: U2.29
GPIO35: D12.2 R10.1 SW4.1 U2.31 | length 824.9
  Top Layer w10: U2.31 1708.46,465.75 1760,414.21 1760,236.27 1801.27,195 R10.1 1828.73,195 1853.73,170 1945,170 D12.2 2066.57,112.8 2094.41,84.96 SW4.1@2230,84.96
GPIO36: D11.2 R9.1 SW4.3 U2.32 | length 550.8
  Top Layer w10: U2.32 1735.94,499.21 1772.46,462.7 1810.8,462.7 R9.1 1876.96,458.5 1880.66,462.2 D11.2 1926.89,460.31 2224.73,460.31 SW4.3@2230,455.04
GPIO37: U2.33
GPIO38: D14.2 J5.1 U2.34 | length 1066.2
  Top Layer w10: v1(1640,540) 1643.7,540 1669.84,566.14 U2.34
  Bottom Layer w10: v1(1640,540) 1861.36,540 2049.5,351.86 2049.5,314.99 2023.43,288.93 1834.24,288.93 1815,269.69 D14.2 1894.74,247.8 1907.54,235 J5.1
GPIO39: U2.35
GPIO40: U2.36
GPIO41: U2.37
GPIO42: U2.38
GPIO43: D8.2 J2.1 U2.39 | length 385.9
  Top Layer w10: U2.39 1708.46,733.46 1801.34,640.59 D8.2 1969.41,640.59 J2.1
GPIO44: D7.2 J2.2 U2.40 | length 353.4
  Top Layer w10: U2.40 1708.46,766.93 1775.39,700 D7.2 ; D7.2@1919.92,700 1934.92,685 J2.2
GPIO45: U2.41
GPIO46: U2.44
GPIO47: U2.27
GPIO48: U2.30
NetC1_2: C1.2 R1.2 R4.2 U1.1 | length 427.7
  Top Layer w10: 408.5,200 411.02,197.48
  Top Layer w20: R4.2 398.5,163.5 408.5,173.5 408.5,200 R1.2 408.99,275.5 408.99,325.87 420,336.88 v1(420,345) ; 411.02,197.48 C1.2
  Bottom Layer w20: v1(420,345) 420,341.34 446.72,314.63 486.73,314.63 494.45,306.91 U1.1
NetC8_2: C8.2 J4.2 U5.5 U6.2 | length 1006.4
  Top Layer w10: U6.2 U6.2@150.95,115 ; U5.5 930,223.35 942.52,210.83 C8.2 940.34,197.81 940.34,122.19 J4.2
  Top Layer w20: U6.2@150.95,115 220.95,45 863.15,45 J4.2
NetD1_2: D1.2 R2.1 | length 69.9
  Bottom Layer w10: R2.1 1008.5,445 D1.2
NetD2_2: D2.2 R3.1 | length 82.8
  Bottom Layer w10: R3.1 998.24,370 D2.2
NetD5_2: D5.2 R7.1 | length 78.8
  Top Layer w10: D5.2 1171.97,250 1188.5,266.53 R7.1
NetD10_2: D10.2 R11.1 SW3.1 SW3.2 | length 728.1
  Top Layer w10: R11.1 1818.81,564.69 1918.11,564.69 D10.2 1949.5,562.8 1986.29,526 2049.44,526 2084,560.56 2084,582.49 2099.5,597.99 2135.83,597.99 2156.42,618.58 SW3.1 SW3.2
NetJ3_A5: J3.A5 R15.2 | length 107.9
  Bottom Layer w10: J3.A5 1535.12,275.51 1535.12,299.93 1543.44,308.24 1553.48,308.24 1586.5,341.27 R15.2
NetJ3_A6: J3.A6 J3.B6 U3.3 | length 484.3
  Top Layer w10: v1(1370,105) 1406.5,141.5 1495.56,141.5 1502.63,134.43 1502.63,134.27 1517.4,119.5 U3.3
  Bottom Layer w10: v1(1370,105) 1424.14,105 1470,150.86 1470,235 ; J3.B6 1456.38,273.7 1456.38,248.62 1470,235 ; J3.A6 1493.94,273.7 1493.94,249.28 1479.65,235 1470,235
NetJ3_A7: J3.A7 J3.B7 U3.1 | length 528.1
  Top Layer w10: v1(1365,45) 1372.65,52.65 1392.25,52.65 1442.6,103 U3.1
  Bottom Layer w10: v1(1365,45) 1413.43,45 1466.87,98.44 1475.21,98.44 1521,144.23 1521,216.28 1514.53,222.75 J3.B7 1513.62,275.51 1513.62,299.93 1505.3,308.24 1505.08,308.24 1498.32,315 1490,315 1476.06,301.06 1476.06,291.06 J3.A7@1475,290 ; J3.A7@1474.25,273.7 J3.A7
NetJ3_B5: J3.B5 R14.2 | length 96
  Bottom Layer w10: R14.2 1378.5,341.27 1415.2,304.57 1415.2,275.51 J3.B5
NetJ3_S1: J3.S1 R12.1 | length 73.9
  Top Layer w10: J3.S1 1660,247.05 1691.6,247.05 1697.46,241.19 1697.46,240.31 1706.27,231.5 R12.1
NetJ3_S2: J3.S2 R13.1 | length 85.5
  Top Layer w10: R13.1 1294.38,278.5 1299.54,273.34 1301.35,273.34 1314.92,259.77 J3.S2
NetJ3_S3: J3.S3 R16.1 | length 97.5
  Top Layer w10: J3.S3 1655.08,83.57 1668.65,70 1712.69,70 1721.5,61.19 R16.1@1721.5,50.27
NetJ3_S4: J3.S4 R17.1 | length 98.2
  Top Layer w10: R17.1 1276.11,40 1314.92,78.81 J3.S4
NetJ4_1: J4.1 U5.4 | length 163.2
  Top Layer w10: J4.1 892.6,172.87 U5.4
NetJ4_3: J4.3 U5.6 | length 170.5
  Top Layer w10: U5.6 967.4,188.1 1035.51,120 J4.3
NetJ6_3: J6.3 U7.4 | length 220.2
  Top Layer w10: J6.3 550.75,642.4 U7.4
NetJ6_4: J6.4 U7.6 | length 210.4
  Top Layer w10: J6.4 629.77,589.72 651.9,567.6 U7.6
NetQ1_1: Q1.1 R5.2 | length 72.9
  Bottom Layer w10: Q1.1 1552.87,781.95 1624.55,781.95 R5.2
NetQ2_1: Q2.1 R6.2 | length 285.6
  Bottom Layer w10: Q2.1 1583,947.4 1686.91,843.5 R6.2
NetR1_1: R1.1 U4.1 | length 71.5
  Top Layer w20: U4.1 R1.1
NetR4_1: R4.1 U6.1 | length 63.6
  Top Layer w10: R4.1@326.5,115 R4.1
  Top Layer w20: U6.1 R4.1@326.5,115
NetR18_2: R18.2 U7.1 | length 195.8
  Top Layer w10: U7.1 822,567.6 889.6,500 R18.2
NetR19_2: R19.2 U7.3 | length 189.8
  Top Layer w10: U7.3 816.15,640 906.57,640 929.5,617.07 941.57,605 R19.2
RTS_FTDI: D4.2 J1.2 Q1.2 R6.1 | length 468.3
  Bottom Layer w10: Q1.2 1618.61,707.6 1687.51,776.5 R6.1 1760.18,781.69 1791.69,781.69 1835.91,825.91 1853.11,825.91 D4.2 1856.1,828.9 1968.9,828.9 J1.2
pads on no net: J3.A8 J3.B8

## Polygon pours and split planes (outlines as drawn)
no net on Bottom Layer "NONET_L04_P005" (solid, shelved, pour order 5): 0,0 0,1003.43 2494.51,998.13 2495,0
no net on Top Layer "NONET_L01_P006" (solid, shelved, pour order 6): 0,0 0,1003.43 2494.51,998.13 2495,0
GND on Top Layer "NONET_L01_P007" (solid, shelved, pour order 7): 1515,790 1515,600 1425,510 1390,510 1390,565 1355,600 1315,600 1315,790
GND on 3.3V (split plane): 2474.43,978.08 2474.89,20.1 20.1,20.1 20.1,983.29
3.3V on GND (split plane): 2474.43,978.08 2474.89,20.1 20.1,20.1 20.1,983.29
